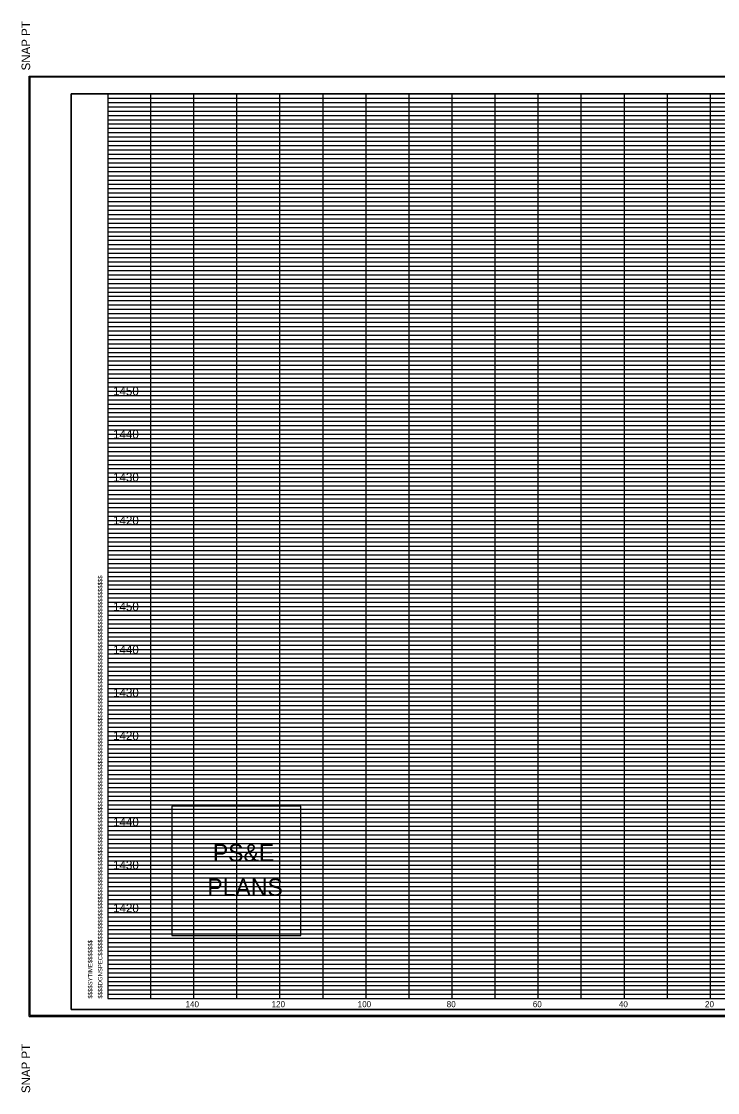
# Model space of a CAD drawing. Extents: x 980 to 1324, y 978 to 1227.
# Drawn here: x 979.9 to 1141.7, y 978.2 to 1226.8 of the extents above; entities that cross this region are included whole.
import ezdxf

# ---------------------------------------------------------------- set-up
doc = ezdxf.new("R2010")
doc.units = 0
for name, color, linetype in [('DESIGN - SHEET - Corner Text', 7, 'Continuous'), ('DESIGN - SHEET - Light Grid', 7, 'Continuous'), ('DESIGN - SHEET - Linework', 7, 'Continuous'), ('DESIGN - SHEET - Plot Shape', 7, 'Continuous'), ('DESIGN - TYPICAL - Finished Grade and Subgrade', 7, 'Continuous')]:
    doc.layers.add(name, color=color, linetype=linetype)

# ---------------------------------------------------------------- blocks, each defined once
blk = doc.blocks.new('XSTSHT')
at = {"layer": 'DESIGN - SHEET - Light Grid'}
for p, q in [((0, 20.9), (8, 20.9)), ((8, 20.9), (16, 20.9)), ((0, 20.8), (8, 20.8)), ((0, 20.7), (8, 20.7)), ((8, 20.8), (16, 20.8)), ((8, 20.7), (16, 20.7)), ((0, 20.6), (8, 20.6)), ((0, 20.5), (8, 20.5)), ((0, 20.4), (8, 20.4)), ((8, 20.6), (16, 20.6)), ((8, 20.5), (16, 20.5)), ((8, 20.4), (16, 20.4)), ((0, 20.3), (8, 20.3)), ((0, 20.2), (8, 20.2)), ((8, 20.3), (16, 20.3)), ((8, 20.2), (16, 20.2)), ((0, 20.1), (8, 20.1)), ((0, 19.9), (8, 19.9)), ((8, 20.1), (16, 20.1)), ((8, 19.9), (16, 19.9)), ((0, 19.8), (8, 19.8)), ((0, 19.7), (8, 19.7)), ((8, 19.8), (16, 19.8)), ((8, 19.7), (16, 19.7)), ((0, 19.6), (8, 19.6)), ((0, 19.5), (8, 19.5)), ((0, 19.4), (8, 19.4)), ((8, 19.6), (16, 19.6)), ((8, 19.5), (16, 19.5)), ((8, 19.4), (16, 19.4)), ((0, 19.3), (8, 19.3)), ((0, 19.2), (8, 19.2)), ((8, 19.3), (16, 19.3)), ((8, 19.2), (16, 19.2)), ((0, 19.1), (8, 19.1)), ((0, 18.9), (8, 18.9)), ((8, 19.1), (16, 19.1)), ((8, 18.9), (16, 18.9)), ((0, 18.8), (8, 18.8)), ((0, 18.7), (8, 18.7)), ((8, 18.8), (16, 18.8)), ((8, 18.7), (16, 18.7)), ((0, 18.6), (8, 18.6)), ((0, 18.5), (8, 18.5)), ((0, 18.4), (8, 18.4)), ((8, 18.6), (16, 18.6)), ((8, 18.5), (16, 18.5)), ((8, 18.4), (16, 18.4)), ((0, 18.3), (8, 18.3)), ((0, 18.2), (8, 18.2)), ((8, 18.3), (16, 18.3)), ((8, 18.2), (16, 18.2)), ((0, 18.1), (8, 18.1)), ((8, 18.1), (16, 18.1)), ((0, 17.9), (8, 17.9)), ((0, 17.8), (8, 17.8)), ((0, 17.7), (8, 17.7)), ((8, 17.9), (16, 17.9)), ((8, 17.8), (16, 17.8)), ((8, 17.7), (16, 17.7)), ((0, 17.6), (8, 17.6)), ((0, 17.5), (8, 17.5)), ((8, 17.6), (16, 17.6)), ((8, 17.5), (16, 17.5)), ((0, 17.4), (8, 17.4)), ((0, 17.3), (8, 17.3)), ((0, 17.2), (8, 17.2)), ((8, 17.4), (16, 17.4)), ((8, 17.3), (16, 17.3)), ((8, 17.2), (16, 17.2)), ((0, 17.1), (8, 17.1)), ((8, 17.1), (16, 17.1)), ((0, 16.9), (8, 16.9)), ((0, 16.8), (8, 16.8)), ((0, 16.7), (8, 16.7)), ((8, 16.9), (16, 16.9)), ((8, 16.8), (16, 16.8)), ((8, 16.7), (16, 16.7)), ((0, 16.6), (8, 16.6)), ((0, 16.5), (8, 16.5)), ((8, 16.6), (16, 16.6)), ((8, 16.5), (16, 16.5)), ((0, 16.4), (8, 16.4)), ((0, 16.3), (8, 16.3)), ((0, 16.2), (8, 16.2)), ((8, 16.4), (16, 16.4)), ((8, 16.3), (16, 16.3)), ((8, 16.2), (16, 16.2)), ((0, 16.1), (8, 16.1)), ((8, 16.1), (16, 16.1)), ((0, 15.9), (8, 15.9)), ((0, 15.8), (8, 15.8)), ((0, 15.7), (8, 15.7)), ((8, 15.9), (16, 15.9)), ((8, 15.8), (16, 15.8)), ((8, 15.7), (16, 15.7)), ((0, 15.6), (8, 15.6)), ((0, 15.5), (8, 15.5)), ((8, 15.6), (16, 15.6)), ((8, 15.5), (16, 15.5)), ((0, 15.4), (8, 15.4)), ((0, 15.3), (8, 15.3)), ((0, 15.2), (8, 15.2)), ((8, 15.4), (16, 15.4)), ((8, 15.3), (16, 15.3)), ((8, 15.2), (16, 15.2)), ((0, 15.1), (8, 15.1)), ((8, 15.1), (16, 15.1)), ((0, 14.9), (8, 14.9)), ((0, 14.8), (8, 14.8)), ((0, 14.7), (8, 14.7)), ((8, 14.9), (16, 14.9)), ((8, 14.8), (16, 14.8)), ((8, 14.7), (16, 14.7)), ((0, 14.6), (8, 14.6)), ((0, 14.5), (8, 14.5)), ((8, 14.6), (16, 14.6)), ((8, 14.5), (16, 14.5)), ((0, 14.4), (8, 14.4)), ((0, 14.3), (8, 14.3)), ((0, 14.2), (8, 14.2)), ((8, 14.4), (16, 14.4)), ((8, 14.3), (16, 14.3)), ((8, 14.2), (16, 14.2)), ((0, 14.1), (8, 14.1)), ((8, 14.1), (16, 14.1)), ((0, 13.9), (8, 13.9)), ((0, 13.8), (8, 13.8)), ((0, 13.7), (8, 13.7)), ((8, 13.9), (16, 13.9)), ((8, 13.8), (16, 13.8)), ((8, 13.7), (16, 13.7)), ((0, 13.6), (8, 13.6)), ((0, 13.5), (8, 13.5)), ((8, 13.6), (16, 13.6)), ((8, 13.5), (16, 13.5)), ((0, 13.4), (8, 13.4)), ((0, 13.3), (8, 13.3)), ((0, 13.2), (8, 13.2)), ((8, 13.4), (16, 13.4)), ((8, 13.3), (16, 13.3)), ((8, 13.2), (16, 13.2)), ((0, 13.1), (8, 13.1)), ((8, 13.1), (16, 13.1)), ((0, 12.9), (8, 12.9)), ((0, 12.8), (8, 12.8)), ((0, 12.7), (8, 12.7)), ((8, 12.9), (16, 12.9)), ((8, 12.8), (16, 12.8)), ((8, 12.7), (16, 12.7)), ((0, 12.6), (8, 12.6)), ((0, 12.5), (8, 12.5)), ((8, 12.6), (16, 12.6)), ((8, 12.5), (16, 12.5)), ((0, 12.4), (8, 12.4)), ((0, 12.3), (8, 12.3)), ((0, 12.2), (8, 12.2)), ((8, 12.4), (16, 12.4)), ((8, 12.3), (16, 12.3)), ((8, 12.2), (16, 12.2)), ((0, 12.1), (8, 12.1)), ((8, 12.1), (16, 12.1)), ((0, 11.9), (8, 11.9)), ((0, 11.8), (8, 11.8)), ((0, 11.7), (8, 11.7)), ((8, 11.9), (16, 11.9)), ((8, 11.8), (16, 11.8)), ((8, 11.7), (16, 11.7)), ((0, 11.6), (8, 11.6)), ((0, 11.5), (8, 11.5)), ((8, 11.6), (16, 11.6)), ((8, 11.5), (16, 11.5)), ((0, 11.4), (8, 11.4)), ((0, 11.3), (8, 11.3)), ((0, 11.2), (8, 11.2)), ((8, 11.4), (16, 11.4)), ((8, 11.3), (16, 11.3)), ((8, 11.2), (16, 11.2)), ((0, 11.1), (8, 11.1)), ((8, 11.1), (16, 11.1)), ((0, 10.9), (8, 10.9)), ((0, 10.8), (8, 10.8)), ((0, 10.7), (8, 10.7)), ((8, 10.9), (16, 10.9)), ((8, 10.8), (16, 10.8)), ((8, 10.7), (16, 10.7)), ((0, 10.6), (8, 10.6)), ((0, 10.5), (8, 10.5)), ((8, 10.6), (16, 10.6)), ((8, 10.5), (16, 10.5)), ((0, 10.4), (8, 10.4)), ((0, 10.3), (8, 10.3)), ((0, 10.2), (8, 10.2)), ((8, 10.4), (16, 10.4)), ((8, 10.3), (16, 10.3)), ((8, 10.2), (16, 10.2)), ((0, 10.1), (8, 10.1)), ((8, 10.1), (16, 10.1)), ((0, 9.9), (8, 9.9)), ((0, 9.8), (8, 9.8)), ((0, 9.7), (8, 9.7)), ((8, 9.9), (16, 9.9)), ((8, 9.8), (16, 9.8)), ((8, 9.7), (16, 9.7)), ((0, 9.6), (8, 9.6)), ((0, 9.5), (8, 9.5)), ((8, 9.6), (16, 9.6)), ((8, 9.5), (16, 9.5)), ((0, 9.4), (8, 9.4)), ((0, 9.3), (8, 9.3)), ((0, 9.2), (8, 9.2)), ((8, 9.4), (16, 9.4)), ((8, 9.3), (16, 9.3)), ((8, 9.2), (16, 9.2)), ((0, 9.1), (8, 9.1)), ((8, 9.1), (16, 9.1)), ((0, 8.9), (8, 8.9)), ((0, 8.8), (8, 8.8)), ((8, 8.9), (16, 8.9)), ((8, 8.8), (16, 8.8)), ((0, 8.7), (8, 8.7)), ((0, 8.6), (8, 8.6)), ((0, 8.5), (8, 8.5)), ((8, 8.7), (16, 8.7)), ((8, 8.6), (16, 8.6)), ((8, 8.5), (16, 8.5)), ((0, 8.4), (8, 8.4)), ((0, 8.3), (8, 8.3)), ((8, 8.4), (16, 8.4)), ((8, 8.3), (16, 8.3)), ((0, 8.2), (8, 8.2)), ((0, 8.1), (8, 8.1)), ((8, 8.2), (16, 8.2)), ((8, 8.1), (16, 8.1)), ((0, 7.9), (8, 7.9)), ((0, 7.8), (8, 7.8)), ((8, 7.9), (16, 7.9)), ((8, 7.8), (16, 7.8)), ((0, 7.7), (8, 7.7)), ((0, 7.6), (8, 7.6)), ((0, 7.5), (8, 7.5)), ((8, 7.7), (16, 7.7)), ((8, 7.6), (16, 7.6)), ((8, 7.5), (16, 7.5)), ((0, 7.4), (8, 7.4)), ((0, 7.3), (8, 7.3)), ((8, 7.4), (16, 7.4)), ((8, 7.3), (16, 7.3)), ((0, 7.2), (8, 7.2)), ((0, 7.1), (8, 7.1)), ((8, 7.2), (16, 7.2)), ((8, 7.1), (16, 7.1)), ((0, 6.9), (8, 6.9)), ((0, 6.8), (8, 6.8)), ((8, 6.9), (16, 6.9)), ((8, 6.8), (16, 6.8)), ((0, 6.7), (8, 6.7)), ((0, 6.6), (8, 6.6)), ((0, 6.5), (8, 6.5)), ((8, 6.7), (16, 6.7)), ((8, 6.6), (16, 6.6)), ((8, 6.5), (16, 6.5)), ((0, 6.4), (8, 6.4)), ((0, 6.3), (8, 6.3)), ((8, 6.4), (16, 6.4)), ((8, 6.3), (16, 6.3)), ((0, 6.2), (8, 6.2)), ((0, 6.1), (8, 6.1)), ((8, 6.2), (16, 6.2)), ((8, 6.1), (16, 6.1)), ((0, 5.9), (8, 5.9)), ((0, 5.8), (8, 5.8)), ((8, 5.9), (16, 5.9)), ((8, 5.8), (16, 5.8)), ((0, 5.7), (8, 5.7)), ((0, 5.6), (8, 5.6)), ((0, 5.5), (8, 5.5)), ((8, 5.7), (16, 5.7)), ((8, 5.6), (16, 5.6)), ((8, 5.5), (16, 5.5)), ((0, 5.4), (8, 5.4)), ((0, 5.3), (8, 5.3)), ((8, 5.4), (16, 5.4)), ((8, 5.3), (16, 5.3)), ((0, 5.2), (8, 5.2)), ((0, 5.1), (8, 5.1)), ((8, 5.2), (16, 5.2)), ((8, 5.1), (16, 5.1)), ((0, 4.9), (8, 4.9)), ((0, 4.8), (8, 4.8)), ((8, 4.9), (16, 4.9)), ((8, 4.8), (16, 4.8)), ((0, 4.7), (8, 4.7)), ((0, 4.6), (8, 4.6)), ((0, 4.5), (8, 4.5)), ((8, 4.7), (16, 4.7)), ((8, 4.6), (16, 4.6)), ((8, 4.5), (16, 4.5)), ((0, 4.4), (8, 4.4)), ((0, 4.3), (8, 4.3)), ((8, 4.4), (16, 4.4)), ((8, 4.3), (16, 4.3)), ((0, 4.2), (8, 4.2)), ((0, 4.1), (8, 4.1)), ((8, 4.2), (16, 4.2)), ((8, 4.1), (16, 4.1)), ((0, 3.9), (8, 3.9)), ((0, 3.8), (8, 3.8)), ((8, 3.9), (16, 3.9)), ((8, 3.8), (16, 3.8)), ((0, 3.7), (8, 3.7)), ((0, 3.6), (8, 3.6)), ((0, 3.5), (8, 3.5)), ((8, 3.7), (16, 3.7)), ((8, 3.6), (16, 3.6)), ((8, 3.5), (16, 3.5)), ((0, 3.4), (8, 3.4)), ((0, 3.3), (8, 3.3)), ((8, 3.4), (16, 3.4)), ((8, 3.3), (16, 3.3)), ((0, 3.2), (8, 3.2)), ((0, 3.1), (8, 3.1)), ((8, 3.2), (16, 3.2)), ((8, 3.1), (16, 3.1)), ((0, 2.9), (8, 2.9)), ((0, 2.8), (8, 2.8)), ((8, 2.9), (16, 2.9)), ((8, 2.8), (16, 2.8)), ((0, 2.7), (8, 2.7)), ((0, 2.6), (8, 2.6)), ((0, 2.5), (8, 2.5)), ((8, 2.7), (16, 2.7)), ((8, 2.6), (16, 2.6)), ((8, 2.5), (16, 2.5)), ((0, 2.4), (8, 2.4)), ((0, 2.3), (8, 2.3)), ((8, 2.4), (16, 2.4)), ((8, 2.3), (16, 2.3)), ((0, 2.2), (8, 2.2)), ((0, 2.1), (8, 2.1)), ((8, 2.2), (16, 2.2)), ((8, 2.1), (16, 2.1)), ((0, 1.9), (8, 1.9)), ((0, 1.8), (8, 1.8)), ((8, 1.9), (16, 1.9)), ((8, 1.8), (16, 1.8)), ((0, 1.7), (8, 1.7)), ((0, 1.6), (8, 1.6)), ((0, 1.5), (8, 1.5)), ((8, 1.7), (16, 1.7)), ((8, 1.6), (16, 1.6)), ((8, 1.5), (16, 1.5)), ((0, 1.4), (8, 1.4)), ((0, 1.3), (8, 1.3)), ((8, 1.4), (16, 1.4)), ((8, 1.3), (16, 1.3)), ((0, 1.2), (8, 1.2)), ((0, 1.1), (8, 1.1)), ((8, 1.2), (16, 1.2)), ((8, 1.1), (16, 1.1)), ((0, 0.9), (8, 0.9)), ((0, 0.8), (8, 0.8)), ((8, 0.9), (16, 0.9)), ((8, 0.8), (16, 0.8)), ((0, 0.7), (8, 0.7)), ((0, 0.6), (8, 0.6)), ((0, 0.5), (8, 0.5)), ((8, 0.7), (16, 0.7)), ((8, 0.6), (16, 0.6)), ((8, 0.5), (16, 0.5)), ((0, 0.4), (8, 0.4)), ((0, 0.3), (8, 0.3)), ((8, 0.4), (16, 0.4)), ((8, 0.3), (16, 0.3)), ((0, 0.2), (8, 0.2)), ((0, 0.1), (8, 0.1)), ((8, 0.2), (16, 0.2)), ((8, 0.1), (16, 0.1))]:
    blk.add_line(p, q, dxfattribs=at)
at = {"layer": 'DESIGN - SHEET - Linework'}
for p, q in [((-1.823, -0.414), (-1.823, 21.414)), ((-1.823, 21.414), (32.217, 21.414)), ((1, 0), (1, 21)), ((2, 0), (2, 21)), ((3, 0), (3, 21)), ((4, 0), (4, 21)), ((5, 0), (5, 21)), ((6, 0), (6, 21)), ((7, 0), (7, 21)), ((8, 0), (8, 21)), ((9, 0), (9, 21)), ((10, 0), (10, 21)), ((11, 0), (11, 21)), ((12, 0), (12, 21)), ((13, 0), (13, 21)), ((14, 0), (14, 21)), ((0, 20), (28, 20)), ((0, 19), (32, 19)), ((0, 18), (32, 18)), ((0, 17), (32, 17)), ((0, 16), (32, 16)), ((0, 15), (32, 15)), ((0, 14), (32, 14)), ((0, 13), (32, 13)), ((0, 12), (32, 12)), ((0, 11), (32, 11)), ((0, 10), (32, 10)), ((0, 9), (32, 9)), ((0, 8), (32, 8)), ((0, 7), (32, 7)), ((0, 6), (32, 6)), ((0, 5), (32, 5)), ((0, 4), (32, 4)), ((0, 3), (32, 3)), ((0, 2), (32, 2)), ((0, 1), (32, 1)), ((-1.823, -0.414), (32.217, -0.414))]:
    blk.add_line(p, q, dxfattribs=at)
blk.add_lwpolyline([(0, 21), (0, 0), (32, 0), (32, 21), (0, 21)], dxfattribs=at)
at = {"layer": 'DESIGN - SHEET - Plot Shape'}
for points in [[(-1.803, 21.394), (32.197, 21.394), (32.197, -0.394), (-1.803, -0.394)], [(-0.85, 21), (32, 21), (32, -0.25), (-0.85, -0.25)]]:
    blk.add_lwpolyline(points, close=True, dxfattribs=at)
at = {"layer": 'DESIGN - SHEET - Corner Text'}
for s, height, p in [('  SNAP PT', 0.2, (-1.803, 21.394)), ('$$$$DGNSPEC$$$$$$$$$$$$$$$$$$$$$$$$$$$$$$$$$$$$$$$$$$$$$$$$$$$$$$$$$$$$$$$$$$$$$$$$$$$$$$$$$$$$$$$$$$$$$$$$$$$$$$$$$$$$$$$$$$$', 0.100002, (-0.126, 0)), ('$$$$SYTIME$$$$$$$', 0.1, (-0.358, 0)), ('SNAP PT  ', 0.2, (-1.803, -2.194))]:
    blk.add_text(s, height=height, rotation=90, dxfattribs=at).set_placement(p)

msp = doc.modelspace()

# ---------------------------------------------------------------- linework, layer by layer
at = {"layer": 'DESIGN - SHEET - Corner Text'}
msp.add_lwpolyline([(1014.88, 1044.67), (1014.88, 1014.67), (1044.88, 1014.67), (1044.88, 1044.67)], close=True, dxfattribs=at)
at = {"layer": 'DESIGN - SHEET - Plot Shape'}
msp.add_lwpolyline([(991.5, 997.5), (1320, 997.5), (1320, 1210), (991.5, 1210)], close=True, dxfattribs=at)

# ---------------------------------------------------------------- block references
at = {"layer": 'DESIGN - TYPICAL - Finished Grade and Subgrade', "xscale": 10, "yscale": 10}
msp.add_blockref('XSTSHT', (1000, 1000), dxfattribs=at)

# ---------------------------------------------------------------- texts
at = {"layer": 'DESIGN - SHEET - Corner Text'}
for s, height, p in [('1450', 2, (1001.25, 1140)), ('1440', 2, (1001.25, 1130)), ('1430', 2, (1001.25, 1120)), ('1420', 2, (1001.25, 1110)), ('1450', 2, (1001.25, 1090)), ('1440', 2, (1001.25, 1080)), ('1430', 2, (1001.25, 1070)), ('1420', 2, (1001.25, 1060)), ('1440', 2, (1001.25, 1040)), ('PS&E', 4, (1024.4, 1031.84)), ('1430', 2, (1001.25, 1030)), ('PLANS', 4, (1023.12, 1023.84)), ('1420', 2, (1001.25, 1020)), ('140', 1.4, (1018.06, 998)), ('120', 1.4, (1038.06, 998)), ('100', 1.4, (1058.06, 998)), ('80', 1.4, (1078.74, 998)), ('60', 1.4, (1098.74, 998)), ('40', 1.4, (1118.74, 998)), ('20', 1.4, (1138.74, 998))]:
    msp.add_text(s, height=height, dxfattribs=at).set_placement(p)

doc.saveas('drawing.dxf')
